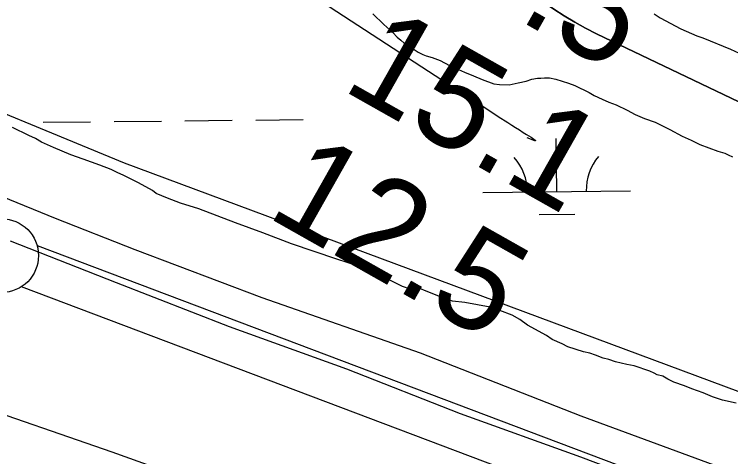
# Model space of a CAD drawing. Extents: x 3651524 to 3689615, y 505651 to 531377.
# Drawn here: x 3660133.1 to 3660618.3, y 514732.1 to 515031.9 of the extents above; entities that cross this region are included whole.
import ezdxf

# ---------------------------------------------------------------- set-up
doc = ezdxf.new("R2010")
doc.units = 0
for name, color, linetype in [('V-FLOD-BASE', 7, 'Continuous'), ('V-LEVE-TOET', 7, 'Continuous'), ('V-RIVR-RANG', 7, 'Continuous'), ('V-SITE-VEGE', 7, 'Continuous'), ('V-SURV-LINE', 7, 'Continuous'), ('V-TOPO-DPTH', 7, 'Continuous'), ('V-TOPO-MINR', 7, 'Continuous'), ('V-WETL-SWMP', 7, 'Continuous')]:
    doc.layers.add(name, color=color, linetype=linetype)

msp = doc.modelspace()

# ---------------------------------------------------------------- linework, layer by layer
at = {"layer": 'V-FLOD-BASE'}
msp.add_lwpolyline([(3661759.69, 514238.096), (3661685.17, 514268.427), (3661584.668, 514310.075), (3661485.832, 514352.381), (3661429.03, 514378.208), (3661353.899, 514411.847), (3661277.474, 514441.293), (3661234.511, 514458.267), (3661152.286, 514490.228), (3661055.668, 514528.007), (3660957.331, 514563.251), (3660887.897, 514590.852), (3660799.84, 514624.157), (3660719.21, 514654.428), (3660647.671, 514682.326), (3660584.937, 514705.974), (3660516.859, 514731.656), (3660435.263, 514761.018), (3660358.395, 514791.417), (3660278.892, 514820.013), (3660202.246, 514849.934), (3660130.479, 514878.072)], dxfattribs=at)
at = {"layer": 'V-LEVE-TOET'}
for points in [[(3661743.617, 514270.373), (3661645.068, 514314.548), (3661553.831, 514351.703), (3661473.546, 514385.722), (3661369.554, 514436.632), (3661265.6, 514480.727), (3661235.644, 514492.63), (3661170.308, 514515.649), (3661061.504, 514554.484), (3660927.862, 514603.429), (3660822.427, 514644.983), (3660743.393, 514673.565), (3660637.253, 514715.141), (3660517.101, 514759.468), (3660408.176, 514802.3), (3660300.978, 514839.678), (3660215.011, 514872.219), (3660160.898, 514893.505), (3660125.151, 514908.159), (3660097.079, 514920.24), (3660071.802, 514931.537)], [(3661494.892, 514229.857), (3661453.383, 514248.435), (3661403.43, 514275.474), (3661364.893, 514299.366), (3661340.571, 514311.105), (3661277.308, 514340.877), (3661179.983, 514378.675), (3661080.94, 514421.927), (3661010.99, 514447.898), (3660937.5, 514473.266), (3660829.505, 514515.6), (3660754.204, 514543.369), (3660675.184, 514572.42), (3660580.937, 514602.849), (3660488.542, 514632.287), (3660389.969, 514667.537), (3660296.957, 514700.045), (3660199.319, 514735.035), (3660098.623, 514769.878)]]:
    msp.add_lwpolyline(points, dxfattribs=at)
at = {"layer": 'V-SITE-VEGE'}
for points in [[(3660375.943, 515032.161), (3660383.416, 515025.038), (3660389.396, 515019.492), (3660392.376, 515016.334), (3660395.005, 515014.342), (3660397.252, 515012.357), (3660400.648, 515010.34), (3660406.675, 515006.328), (3660409.698, 515004.706), (3660411.977, 515003.872), (3660416.161, 515002.6), (3660421.476, 515000.528), (3660427.908, 514997.272), (3660438.142, 514992.754), (3660444.211, 514990.278), (3660449.898, 514987.81), (3660457.875, 514984.893), (3660461.7, 514984.4), (3660468.217, 514984.211), (3660474.398, 514985.567), (3660479.799, 514986.565), (3660483.682, 514987.99), (3660487.538, 514988.645), (3660489.84, 514988.582), (3660492.15, 514988.897), (3660495.603, 514988.797), (3660499.799, 514987.908), (3660508.555, 514985.354), (3660512.728, 514983.697), (3660522.567, 514978.809), (3660525.965, 514976.792), (3660531.267, 514974.336), (3660535.814, 514972.286), (3660540.755, 514970.609), (3660548.329, 514966.937), (3660553.619, 514964.096), (3660560.062, 514961.225), (3660567.281, 514958.714), (3660577.12, 514953.823), (3660585.437, 514949.363), (3660591.495, 514946.502), (3660597.555, 514943.638), (3660609.705, 514939.067), (3660614.274, 514937.783), (3660616.542, 514936.567), (3660619.577, 514935.328)], [(3660320.792, 514876.378), (3660301.43, 514883.843), (3660282.814, 514890.522), (3660258.14, 514900.061), (3660245.583, 514903.877), (3660236.851, 514907.198), (3660229.269, 514910.488), (3660226.639, 514912.482), (3660217.196, 514917.746), (3660207.355, 514922.634), (3660202.809, 514924.684), (3660198.645, 514926.722), (3660191.051, 514929.628), (3660179.654, 514933.796), (3660171.296, 514936.72), (3660165.609, 514939.19), (3660159.541, 514941.666), (3660151.586, 514945.351), (3660147.435, 514947.773), (3660142.888, 514949.823), (3660131.909, 514955.13)], [(3660622.061, 514768.289), (3660612.91, 514770.474), (3660606.064, 514772.587), (3660599.621, 514775.461), (3660592.017, 514777.982), (3660587.085, 514780.042), (3660579.866, 514782.553), (3660575.7, 514784.593), (3660572.305, 514786.61), (3660568.491, 514787.487), (3660566.609, 514788.691), (3660563.572, 514789.932), (3660552.933, 514793.692), (3660547.968, 514794.603), (3660540.344, 514796.359), (3660535.785, 514798.028), (3660531.971, 514798.902), (3660526.659, 514800.975), (3660522.856, 514802.236), (3660518.659, 514803.123), (3660508.012, 514806.502), (3660504.229, 514808.53), (3660497.403, 514811.413), (3660493.645, 514814.209), (3660480.794, 514821.105), (3660475.537, 514825.092), (3660470.243, 514827.933), (3660461.893, 514831.244), (3660455.43, 514833.35), (3660438.249, 514836.53), (3660429.834, 514837.542), (3660425.647, 514838.814), (3660421.857, 514840.456), (3660415.403, 514842.947), (3660410.474, 514845.007), (3660405.915, 514846.674), (3660402.857, 514847.147), (3660401.278, 514845.656), (3660395.954, 514847.346), (3660372.496, 514859.15), (3660351.58, 514865.894), (3660320.792, 514876.378)]]:
    msp.add_lwpolyline(points, dxfattribs=at)
at = {"layer": 'V-SURV-LINE'}
for points in [[(3660148.471, 514875.327), (3661287.512, 514444.608)], [(3661276.893, 514416.55), (3660137.852, 514847.269)]]:
    msp.add_lwpolyline(points, dxfattribs=at)
msp.add_circle((3660124.478, 514868.363), 25, dxfattribs=at)
at = {"layer": 'V-TOPO-DPTH'}
msp.add_lwpolyline([(3662644.311, 514103.201), (3662090.264, 514319.377), (3662015.342, 514348.705), (3661940.463, 514378.144), (3661865.65, 514407.747), (3661790.88, 514437.461), (3661719.927, 514465.749), (3661680.755, 514481.612), (3661641.701, 514497.756), (3661602.823, 514514.32), (3661564.064, 514531.166), (3661495.695, 514561.32), (3661422.991, 514593.784), (3661350.49, 514626.689), (3661278.293, 514660.256), (3661206.299, 514694.263), (3660527.5, 515018.706), (3660520.041, 515022.492), (3660512.716, 515026.508), (3660505.59, 515030.868), (3660498.598, 515035.458), (3660317.459, 515160.641), (3660220.777, 515229.04), (3660125.134, 515298.829)], dxfattribs=at)
at = {"layer": 'V-TOPO-MINR'}
for points in [[(3659380.36, 515670.29), (3659390.806, 515661.585), (3659396.1, 515657.33), (3659401.488, 515653.202), (3659407.019, 515649.267), (3659412.645, 515645.46), (3660437.591, 514977.855), (3660443.421, 514974.06), (3660449.253, 514970.269), (3660455.089, 514966.482), (3660460.926, 514962.699), (3660467.433, 514958.485), (3660470.024, 514956.82), (3660472.624, 514955.168), (3660475.236, 514953.536), (3660477.856, 514951.917), (3660480.109, 514950.535), (3660483.081, 514948.657), (3660486.001, 514946.698), (3660486.111, 514946.437), (3660486.109, 514946.237), (3660485.941, 514946.13), (3660485.661, 514946.083), (3660480.577, 514948.259)], [(3660125.134, 515298.829), (3660220.777, 515229.04), (3660317.459, 515160.641), (3660498.598, 515035.458), (3660505.59, 515030.868), (3660512.716, 515026.508), (3660520.041, 515022.492), (3660527.5, 515018.706), (3661206.299, 514694.263), (3661278.293, 514660.256), (3661350.49, 514626.689), (3661422.991, 514593.784), (3661495.695, 514561.32), (3661564.064, 514531.166), (3661602.823, 514514.32), (3661641.701, 514497.756), (3661680.755, 514481.612), (3661719.927, 514465.749), (3661790.88, 514437.461), (3661865.65, 514407.747), (3661940.463, 514378.144), (3662015.342, 514348.705), (3662090.264, 514319.377), (3662644.311, 514103.201)]]:
    msp.add_lwpolyline(points, dxfattribs=at)
at = {"layer": 'V-WETL-SWMP'}
for p, q in [((3660152.704, 514958.724), (3660184.702, 514959.068)), ((3660200.701, 514959.24), (3660232.7, 514959.585)), ((3660248.699, 514959.757), (3660280.697, 514960.101)), ((3660296.696, 514960.274), (3660328.694, 514960.618)), ((3660500.546, 514911.723), (3660500.159, 514947.721)), ((3660450.549, 514911.185), (3660550.543, 514912.261)), ((3660488.713, 514896.164), (3660512.712, 514896.422))]:
    msp.add_line(p, q, dxfattribs=at)
for points in [[(3660566.583, 515032.139), (3660570.598, 515029.619), (3660584.564, 515022.004), (3660595.49, 515017.361), (3660599.54, 515016.042), (3660618.31, 515008.289), (3660624, 515005.48)], [(3661701.85, 514341.948), (3661594.462, 514384.904), (3661385.823, 514480.019), (3661260.025, 514535.247), (3660943.998, 514651.84), (3660652.516, 514765.364), (3660207.623, 514931.048), (3660066.484, 514989.345)]]:
    msp.add_lwpolyline(points, dxfattribs=at)
for centre, start, end in [((3660445.301, 514911.603), 359.84486, 41.38852), ((3660555.781, 514912.792), 139.84486, 181.38852)]:
    msp.add_arc(centre, 35.246, start, end, dxfattribs=at)

# ---------------------------------------------------------------- texts
at = {"layer": 'V-RIVR-RANG'}
for s, p in [('7.5', (3660429.701, 515053.418)), ('15.1', (3660353.847, 514981.421)), ('12.5', (3660302.795, 514895.408))]:
    msp.add_text(s, height=67, rotation=330.52833, dxfattribs=at).set_placement(p)

doc.saveas('drawing.dxf')
